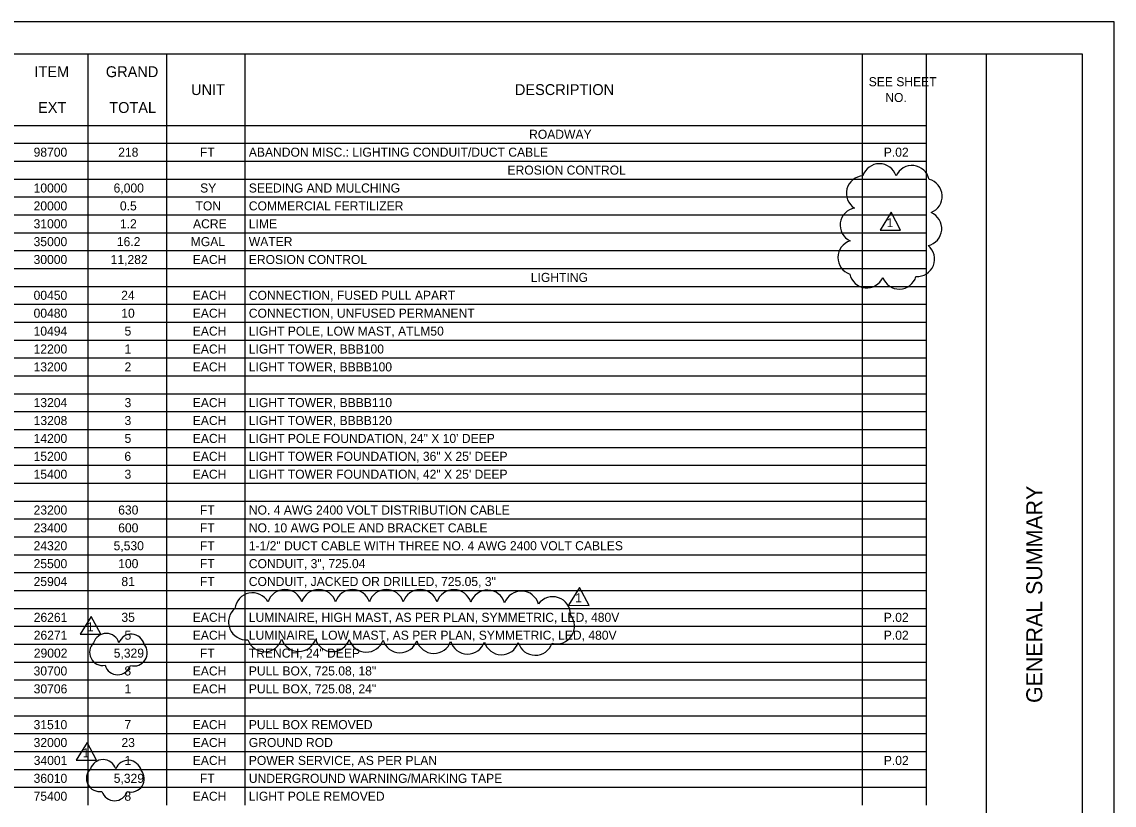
# Model space of a CAD drawing. Extents: x 0 to 34, y 0 to 22.
# Drawn here: x 16.91 to 34, y 9.75 to 22 of the extents above; entities that cross this region are included whole.
import ezdxf

# ---------------------------------------------------------------- set-up
doc = ezdxf.new("R2010")
doc.units = 0
for name, color, linetype in [('Default', 7, 'Continuous'), ('SH_Border', 7, 'Continuous'), ('SH_Cut_Line', 7, 'Continuous'), ('SH_Data', 7, 'Continuous'), ('SH_Text', 7, 'Continuous')]:
    doc.layers.add(name, color=color, linetype=linetype)

msp = doc.modelspace()

# ---------------------------------------------------------------- linework, layer by layer
at = {"layer": 'Default'}
for points in [[(30.508, 19.02), (30.337, 18.741), (30.657, 18.74)], [(25.633, 13.151), (25.462, 12.873), (25.783, 12.871)], [(17.991, 12.699), (17.82, 12.42), (18.141, 12.418)], [(17.926, 10.727), (17.755, 10.449), (18.075, 10.447)]]:
    msp.add_lwpolyline(points, close=True, dxfattribs=at)
for centre, radius, start, end in [((30.327, 19.508), 0.272, 17.5, 162.5), ((30.836, 19.481), 0.272, 11.3773, 156.3773), ((30.082, 19.318), 0.272, 92.9878, 237.9878), ((31.037, 19.271), 0.272, 291.0388, 76.0388), ((29.984, 18.82), 0.272, 99.783, 244.783), ((31.03, 18.765), 0.272, 282.4715, 67.4715), ((29.948, 18.313), 0.272, 107.0971, 252.0971), ((30.918, 18.288), 0.272, 265.9978, 50.9978), ((30.13, 18.109), 0.272, 191.6864, 336.6864), ((30.637, 18.091), 0.272, 199.2165, 344.2165), ((20.515, 12.791), 0.277, 28.8438, 173.8438), ((21.023, 12.842), 0.277, 17.5, 162.5), ((21.552, 12.842), 0.277, 17.5, 162.5), ((22.081, 12.842), 0.277, 17.5, 162.5), ((22.61, 12.842), 0.277, 17.5, 162.5), ((23.139, 12.841), 0.277, 17.3728, 162.3728), ((23.667, 12.839), 0.277, 17.0464, 162.0464), ((24.195, 12.832), 0.277, 16.5318, 161.5318), ((24.723, 12.818), 0.277, 15.5213, 160.5213), ((25.214, 12.728), 0.278, 358.7393, 143.7393), ((20.418, 12.609), 0.277, 130.1459, 275.1459), ((25.278, 12.546), 0.277, 254.532, 39.532), ((18.227, 12.223), 0.208, 17.5, 162.5), ((18.619, 12.212), 0.208, 14.1039, 159.1039), ((20.706, 12.422), 0.277, 198.7139, 343.7139), ((21.237, 12.427), 0.277, 197.3996, 342.3996), ((21.766, 12.424), 0.277, 196.8496, 341.8496), ((22.296, 12.416), 0.277, 196.5252, 341.5252), ((22.825, 12.407), 0.277, 196.3732, 341.3732), ((23.354, 12.396), 0.277, 196.3818, 341.3818), ((23.883, 12.386), 0.277, 196.3997, 341.3997), ((18.174, 12.138), 0.208, 134.5743, 279.5743), ((18.661, 12.13), 0.208, 254.4905, 39.4905), ((24.412, 12.376), 0.277, 196.4321, 341.4321), ((24.941, 12.367), 0.277, 196.531, 341.531), ((18.407, 11.994), 0.208, 197.0681, 342.0681), ((18.178, 10.251), 0.208, 17.5, 162.5), ((18.57, 10.239), 0.208, 14.1039, 159.1039), ((18.125, 10.165), 0.208, 134.5743, 279.5743), ((18.612, 10.158), 0.208, 254.4905, 39.4905), ((18.358, 10.022), 0.208, 197.0681, 342.0681)]:
    msp.add_arc(centre, radius, start, end, dxfattribs=at)
at = {"layer": 'SH_Border'}
msp.add_line((32, 0.5), (32, 21.5), dxfattribs=at)
msp.add_lwpolyline([(1.5, 21.5), (33.5, 21.5), (33.5, 0.5), (1.5, 0.5)], close=True, dxfattribs=at)
at = {"layer": 'SH_Cut_Line'}
msp.add_lwpolyline([(0, 0), (34, 0), (34, 22), (0, 22)], close=True, dxfattribs=at)
at = {"layer": 'SH_Text'}
for p, q in [((13.49, 21.5), (31.057, 21.5)), ((17.941, 21.5), (17.941, 21.22)), ((19.168, 21.5), (19.168, 21.22)), ((20.395, 21.5), (20.395, 21.22)), ((30.057, 21.5), (30.057, 21.22)), ((31.057, 21.5), (31.057, 21.22)), ((17.941, 21.22), (17.941, 20.94)), ((19.168, 21.22), (19.168, 20.94)), ((20.395, 21.22), (20.395, 20.94)), ((30.057, 21.22), (30.057, 20.94)), ((31.057, 21.22), (31.057, 20.94)), ((17.941, 20.94), (17.941, 20.66)), ((19.168, 20.94), (19.168, 20.66)), ((20.395, 20.94), (20.395, 20.66)), ((30.057, 20.94), (30.057, 20.66)), ((31.057, 20.94), (31.057, 20.66)), ((17.941, 20.66), (17.941, 20.38)), ((19.168, 20.66), (19.168, 20.38)), ((20.395, 20.66), (20.395, 20.38)), ((30.057, 20.66), (30.057, 20.38)), ((31.057, 20.66), (31.057, 20.38)), ((13.49, 20.38), (31.057, 20.38)), ((17.941, 20.38), (17.941, 20.101)), ((19.168, 20.38), (19.168, 20.101)), ((20.395, 20.38), (20.395, 20.101)), ((30.057, 20.38), (30.057, 20.101)), ((31.057, 20.38), (31.057, 20.101)), ((13.49, 20.101), (31.057, 20.101)), ((17.941, 20.101), (17.941, 18.701)), ((19.168, 20.101), (19.168, 18.701)), ((20.395, 20.101), (20.395, 18.701)), ((30.057, 20.101), (30.057, 18.701)), ((31.057, 20.101), (31.057, 18.701)), ((13.49, 19.821), (31.057, 19.821)), ((13.49, 19.541), (31.057, 19.541)), ((13.49, 19.261), (31.057, 19.261)), ((13.49, 18.981), (31.057, 18.981)), ((13.49, 18.701), (31.057, 18.701)), ((17.941, 18.701), (17.941, 18.141)), ((19.168, 18.701), (19.168, 18.141)), ((20.395, 18.701), (20.395, 18.141)), ((30.057, 18.701), (30.057, 18.141)), ((31.057, 18.701), (31.057, 18.141)), ((13.49, 18.421), (31.057, 18.421)), ((13.49, 18.141), (31.057, 18.141)), ((17.941, 18.141), (17.941, 17.862)), ((19.168, 18.141), (19.168, 17.862)), ((20.395, 18.141), (20.395, 17.862)), ((30.057, 18.141), (30.057, 17.862)), ((31.057, 18.141), (31.057, 17.862)), ((13.49, 17.862), (31.057, 17.862)), ((17.941, 17.862), (17.941, 17.582)), ((19.168, 17.862), (19.168, 17.582)), ((20.395, 17.862), (20.395, 17.582)), ((30.057, 17.862), (30.057, 17.582)), ((31.057, 17.862), (31.057, 17.582)), ((13.49, 17.582), (31.057, 17.582)), ((17.941, 17.582), (17.941, 17.302)), ((19.168, 17.582), (19.168, 17.302)), ((20.395, 17.582), (20.395, 17.302)), ((30.057, 17.582), (30.057, 17.302)), ((31.057, 17.582), (31.057, 17.302)), ((13.49, 17.302), (31.057, 17.302)), ((17.941, 17.302), (17.941, 17.022)), ((19.168, 17.302), (19.168, 17.022)), ((20.395, 17.302), (20.395, 17.022)), ((30.057, 17.302), (30.057, 17.022)), ((31.057, 17.302), (31.057, 17.022)), ((13.49, 17.022), (31.057, 17.022)), ((17.941, 17.022), (17.941, 16.742)), ((19.168, 17.022), (19.168, 16.742)), ((20.395, 17.022), (20.395, 16.742)), ((30.057, 17.022), (30.057, 16.742)), ((31.057, 17.022), (31.057, 16.742)), ((13.49, 16.742), (31.057, 16.742)), ((17.941, 16.742), (17.941, 16.182)), ((19.168, 16.742), (19.168, 16.182)), ((20.395, 16.742), (20.395, 16.182)), ((30.057, 16.742), (30.057, 16.182)), ((31.057, 16.742), (31.057, 16.182)), ((13.49, 16.462), (31.057, 16.462)), ((13.49, 16.182), (31.057, 16.182)), ((17.941, 16.182), (17.941, 15.902)), ((19.168, 16.182), (19.168, 15.902)), ((20.395, 16.182), (20.395, 15.902)), ((30.057, 16.182), (30.057, 15.902)), ((31.057, 16.182), (31.057, 15.902)), ((13.49, 15.902), (31.057, 15.902)), ((17.941, 15.902), (17.941, 15.623)), ((19.168, 15.902), (19.168, 15.623)), ((20.395, 15.902), (20.395, 15.623)), ((30.057, 15.902), (30.057, 15.623)), ((31.057, 15.902), (31.057, 15.623)), ((13.49, 15.623), (31.057, 15.623)), ((17.941, 15.623), (17.941, 15.343)), ((19.168, 15.623), (19.168, 15.343)), ((20.395, 15.623), (20.395, 15.343)), ((30.057, 15.623), (30.057, 15.343)), ((31.057, 15.623), (31.057, 15.343)), ((13.49, 15.343), (31.057, 15.343)), ((17.941, 15.343), (17.941, 14.783)), ((19.168, 15.343), (19.168, 14.783)), ((20.395, 15.343), (20.395, 14.783)), ((30.057, 15.343), (30.057, 14.783)), ((31.057, 15.343), (31.057, 14.783)), ((13.49, 15.063), (31.057, 15.063)), ((13.49, 14.783), (31.057, 14.783)), ((17.941, 14.783), (17.941, 14.503)), ((19.168, 14.783), (19.168, 14.503)), ((20.395, 14.783), (20.395, 14.503)), ((30.057, 14.783), (30.057, 14.503)), ((31.057, 14.783), (31.057, 14.503)), ((13.49, 14.503), (31.057, 14.503)), ((17.941, 14.503), (17.941, 14.223)), ((19.168, 14.503), (19.168, 14.223)), ((20.395, 14.503), (20.395, 14.223)), ((30.057, 14.503), (30.057, 14.223)), ((31.057, 14.503), (31.057, 14.223)), ((13.49, 14.223), (31.057, 14.223)), ((17.941, 14.223), (17.941, 13.943)), ((19.168, 14.223), (19.168, 13.943)), ((20.395, 14.223), (20.395, 13.943)), ((30.057, 14.223), (30.057, 13.943)), ((31.057, 14.223), (31.057, 13.943)), ((13.49, 13.943), (31.057, 13.943)), ((17.941, 13.943), (17.941, 11.704)), ((19.168, 13.943), (19.168, 11.704)), ((20.395, 13.943), (20.395, 11.704)), ((30.057, 13.943), (30.057, 11.704)), ((31.057, 13.943), (31.057, 11.704)), ((13.49, 13.663), (31.057, 13.663)), ((13.49, 13.384), (31.057, 13.384)), ((13.49, 13.104), (31.057, 13.104)), ((13.49, 12.824), (31.057, 12.824)), ((13.49, 12.544), (31.057, 12.544)), ((13.49, 12.264), (31.057, 12.264)), ((13.49, 11.984), (31.057, 11.984)), ((13.49, 11.704), (31.057, 11.704)), ((17.941, 11.704), (17.941, 11.424)), ((19.168, 11.704), (19.168, 11.424)), ((20.395, 11.704), (20.395, 11.424)), ((30.057, 11.704), (30.057, 11.424)), ((31.057, 11.704), (31.057, 11.424)), ((13.49, 11.424), (31.057, 11.424)), ((17.941, 11.424), (17.941, 10.305)), ((19.168, 11.424), (19.168, 10.305)), ((20.395, 11.424), (20.395, 10.305)), ((30.057, 11.424), (30.057, 10.305)), ((31.057, 11.424), (31.057, 10.305)), ((13.49, 11.145), (31.057, 11.145)), ((13.49, 10.865), (31.057, 10.865)), ((13.49, 10.585), (31.057, 10.585)), ((13.49, 10.305), (31.057, 10.305)), ((17.941, 10.305), (17.941, 10.025)), ((19.168, 10.305), (19.168, 10.025)), ((20.395, 10.305), (20.395, 10.025)), ((30.057, 10.305), (30.057, 10.025)), ((31.057, 10.305), (31.057, 10.025)), ((13.49, 10.025), (31.057, 10.025)), ((17.941, 10.025), (17.941, 9.745)), ((19.168, 10.025), (19.168, 9.745)), ((20.395, 10.025), (20.395, 9.745)), ((30.057, 10.025), (30.057, 9.745)), ((31.057, 10.025), (31.057, 9.745))]:
    msp.add_line(p, q, dxfattribs=at)

# ---------------------------------------------------------------- texts
at = {"layer": 'Default'}
for p in [(30.44, 18.788), (25.566, 12.919), (17.924, 12.467), (17.858, 10.495)]:
    msp.add_text('1', height=0.14, dxfattribs=at).set_placement(p)
at = {"layer": 'SH_Data'}
msp.add_text('GENERAL SUMMARY', height=0.25, rotation=90, dxfattribs=at).set_placement((32.875, 11.344))
at = {"layer": 'SH_Text'}
for s, height, p in [('ITEM', 0.1699, (17.103, 21.135)), ('GRAND', 0.1699, (18.221, 21.135)), ('DESCRIPTION', 0.16992, (24.622, 20.855)), ('SEE SHEET ', 0.1416, (30.159, 20.993)), ('UNIT', 0.1699, (19.554, 20.855)), ('NO.', 0.1416, (30.418, 20.746)), ('EXT', 0.1699, (17.16, 20.575)), ('TOTAL', 0.1699, (18.274, 20.575)), ('ROADWAY', 0.1416, (24.844, 20.17)), ('98700', 0.1416, (17.09, 19.89)), ('218', 0.1416, (18.414, 19.89)), ('FT', 0.1416, (19.692, 19.89)), ('ABANDON MISC.: LIGHTING CONDUIT/DUCT CABLE', 0.1416, (20.458, 19.89)), ('P.02', 0.1416, (30.395, 19.89)), ('EROSION CONTROL', 0.1416, (24.506, 19.61)), ('10000', 0.1416, (17.09, 19.33)), ('6,000', 0.1416, (18.342, 19.33)), ('SY', 0.1416, (19.696, 19.33)), ('SEEDING AND MULCHING', 0.1416, (20.458, 19.33)), ('20000', 0.1416, (17.09, 19.05)), ('0.5', 0.1416, (18.441, 19.05)), ('TON', 0.1416, (19.624, 19.05)), ('COMMERCIAL FERTILIZER', 0.1416, (20.458, 19.05)), ('31000', 0.1416, (17.09, 18.77)), ('1.2', 0.1416, (18.441, 18.77)), ('ACRE', 0.1416, (19.585, 18.77)), ('LIME', 0.1416, (20.458, 18.77)), ('35000', 0.1416, (17.09, 18.491)), ('16.2', 0.1416, (18.393, 18.491)), ('MGAL', 0.1416, (19.549, 18.491)), ('WATER', 0.1416, (20.458, 18.491)), ('30000', 0.1416, (17.09, 18.211)), ('11,282', 0.1416, (18.296, 18.211)), ('EACH', 0.1416, (19.581, 18.211)), ('EROSION CONTROL', 0.1416, (20.458, 18.211)), ('LIGHTING', 0.1416, (24.871, 17.931)), ('00450', 0.1416, (17.09, 17.651)), ('24', 0.1416, (18.461, 17.651)), ('EACH', 0.1416, (19.581, 17.651)), ('CONNECTION, FUSED PULL APART', 0.1416, (20.458, 17.651)), ('00480', 0.1416, (17.09, 17.371)), ('10', 0.1416, (18.462, 17.371)), ('EACH', 0.1416, (19.581, 17.371)), ('CONNECTION, UNFUSED PERMANENT', 0.1416, (20.458, 17.371)), ('10494', 0.1416, (17.09, 17.091)), ('5', 0.142, (18.513, 17.091)), ('EACH', 0.1416, (19.581, 17.091)), ('LIGHT POLE, LOW MAST, ATLM50', 0.1416, (20.458, 17.091)), ('12200', 0.1416, (17.09, 16.811)), ('1', 0.142, (18.512, 16.811)), ('EACH', 0.1416, (19.581, 16.811)), ('LIGHT TOWER, BBB100', 0.1416, (20.458, 16.811)), ('13200', 0.1416, (17.09, 16.531)), ('2', 0.142, (18.513, 16.531)), ('EACH', 0.1416, (19.581, 16.531)), ('LIGHT TOWER, BBBB100', 0.1416, (20.458, 16.531)), ('13204', 0.1416, (17.09, 15.972)), ('3', 0.142, (18.513, 15.972)), ('EACH', 0.1416, (19.581, 15.972)), ('LIGHT TOWER, BBBB110', 0.1416, (20.458, 15.972)), ('13208', 0.1416, (17.091, 15.692)), ('3', 0.142, (18.513, 15.692)), ('EACH', 0.1416, (19.581, 15.692)), ('LIGHT TOWER, BBBB120', 0.1416, (20.458, 15.692)), ('14200', 0.1416, (17.09, 15.412)), ('EACH', 0.1416, (19.581, 15.412)), ('LIGHT POLE FOUNDATION, 24" X 10\' DEEP', 0.1416, (20.458, 15.412)), ('5', 0.142, (18.513, 15.412)), ('15200', 0.1416, (17.09, 15.132)), ('6', 0.142, (18.511, 15.132)), ('EACH', 0.1416, (19.581, 15.132)), ('LIGHT TOWER FOUNDATION, 36" X 25\' DEEP', 0.1416, (20.458, 15.132)), ('15400', 0.1416, (17.09, 14.852)), ('3', 0.142, (18.513, 14.852)), ('EACH', 0.1416, (19.581, 14.852)), ('LIGHT TOWER FOUNDATION, 42" X 25\' DEEP', 0.1416, (20.458, 14.852)), ('23200', 0.1416, (17.09, 14.292)), ('630', 0.1416, (18.414, 14.292)), ('FT', 0.1416, (19.692, 14.292)), ('NO. 4 AWG 2400 VOLT DISTRIBUTION CABLE', 0.1416, (20.458, 14.292)), ('23400', 0.1416, (17.09, 14.013)), ('600', 0.1416, (18.414, 14.013)), ('FT', 0.1416, (19.692, 14.013)), ('NO. 10 AWG POLE AND BRACKET CABLE', 0.1416, (20.458, 14.013)), ('24320', 0.1416, (17.09, 13.733)), ('5,530', 0.1416, (18.342, 13.733)), ('FT', 0.1416, (19.692, 13.733)), ('1-1/2" DUCT CABLE WITH THREE NO. 4 AWG 2400 VOLT CABLES', 0.1416, (20.458, 13.733)), ('25500', 0.1416, (17.09, 13.453)), ('100', 0.1416, (18.414, 13.453)), ('FT', 0.1416, (19.692, 13.453)), ('CONDUIT, 3", 725.04', 0.1416, (20.458, 13.453)), ('25904', 0.1416, (17.09, 13.173)), ('81', 0.1416, (18.464, 13.173)), ('FT', 0.1416, (19.692, 13.173)), ('CONDUIT, JACKED OR DRILLED, 725.05, 3"', 0.1416, (20.458, 13.173)), ('26261', 0.1416, (17.092, 12.613)), ('35', 0.1416, (18.464, 12.613)), ('EACH', 0.1416, (19.581, 12.613)), ('LUMINAIRE, HIGH MAST, AS PER PLAN, SYMMETRIC, LED, 480V', 0.1416, (20.458, 12.613)), ('P.02', 0.1416, (30.395, 12.613)), ('26271', 0.1416, (17.092, 12.333)), ('5', 0.142, (18.513, 12.333)), ('EACH', 0.1416, (19.581, 12.333)), ('LUMINAIRE, LOW MAST, AS PER PLAN, SYMMETRIC, LED, 480V', 0.1416, (20.458, 12.333)), ('P.02', 0.1416, (30.395, 12.333)), ('29002', 0.1416, (17.093, 12.053)), ('5,329', 0.1416, (18.344, 12.053)), ('FT', 0.1416, (19.692, 12.053)), ('TRENCH, 24" DEEP', 0.1416, (20.458, 12.053)), ('30700', 0.1416, (17.09, 11.774)), ('8', 0.142, (18.511, 11.774)), ('EACH', 0.1416, (19.581, 11.774)), ('PULL BOX, 725.08, 18"', 0.1416, (20.458, 11.774)), ('30706', 0.1416, (17.091, 11.494)), ('1', 0.142, (18.512, 11.494)), ('EACH', 0.1416, (19.581, 11.494)), ('PULL BOX, 725.08, 24"', 0.1416, (20.458, 11.494)), ('31510', 0.1416, (17.09, 10.934)), ('7', 0.142, (18.511, 10.934)), ('EACH', 0.1416, (19.581, 10.934)), ('PULL BOX REMOVED', 0.1416, (20.458, 10.934)), ('32000', 0.1416, (17.09, 10.654)), ('23', 0.1416, (18.465, 10.654)), ('EACH', 0.1416, (19.581, 10.654)), ('GROUND ROD', 0.1416, (20.458, 10.654)), ('34001', 0.1416, (17.092, 10.374)), ('1', 0.142, (18.512, 10.374)), ('EACH', 0.1416, (19.581, 10.374)), ('POWER SERVICE, AS PER PLAN', 0.1416, (20.458, 10.374)), ('P.02', 0.1416, (30.395, 10.374)), ('36010', 0.1416, (17.09, 10.094)), ('5,329', 0.1416, (18.344, 10.094)), ('FT', 0.1416, (19.692, 10.094)), ('UNDERGROUND WARNING/MARKING TAPE', 0.1416, (20.458, 10.094)), ('75400', 0.1416, (17.09, 9.814)), ('8', 0.142, (18.511, 9.814)), ('EACH', 0.1416, (19.581, 9.814)), ('LIGHT POLE REMOVED', 0.1416, (20.458, 9.814))]:
    msp.add_text(s, height=height, dxfattribs=at).set_placement(p)

doc.saveas('drawing.dxf')
